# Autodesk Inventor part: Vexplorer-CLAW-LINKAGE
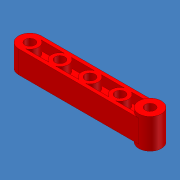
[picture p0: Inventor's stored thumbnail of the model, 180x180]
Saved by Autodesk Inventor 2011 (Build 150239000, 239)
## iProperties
Created: 2007-10
Part Number: Vexplorer-CLAW-LINKAGE
Document SubType Name: Modeling
Material: ABS Plastic
Density: 1.06 g/cm^3
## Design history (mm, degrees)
feature "Base1"
body "Solid1"
